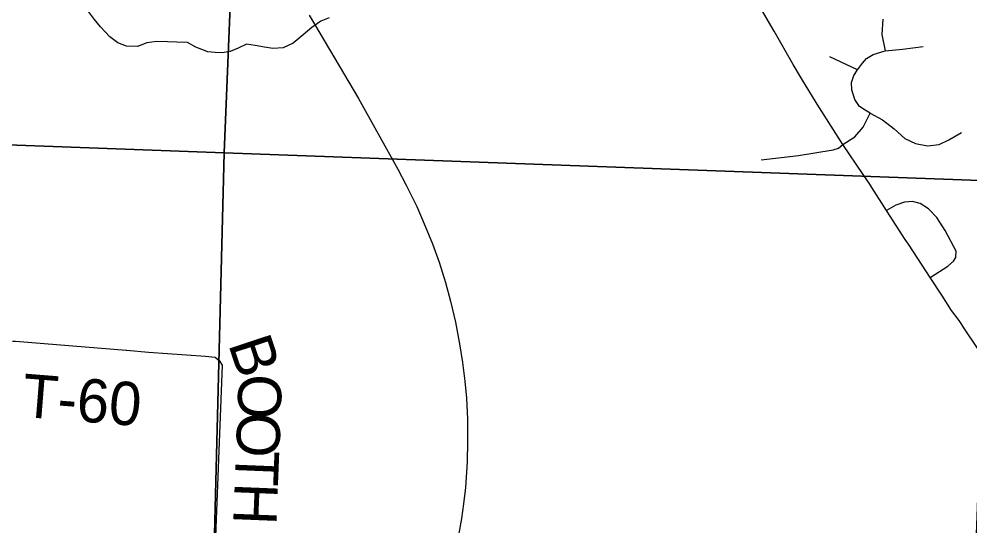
# Model space of a CAD drawing. Extents: x 0 to 34, y 0 to 22.
# Drawn here: x 3.143 to 4.391, y 18.116 to 18.782 of the extents above; entities that cross this region are included whole.
import ezdxf

# ---------------------------------------------------------------- set-up
doc = ezdxf.new("R2010")
doc.units = 0
for name, color, linetype in [('GM_X_City_Street', 7, 'Continuous'), ('GM_X_Minor_River', 7, 'Continuous'), ('GM_X_Rail_Line', 7, 'Continuous'), ('GM_X_Section', 7, 'Continuous'), ('GM_X_Township_Road', 7, 'Continuous'), ('GM_X_Township_Road_Text', 7, 'Continuous'), ('GM_X_US_Route', 7, 'Continuous')]:
    doc.layers.add(name, color=color, linetype=linetype)

msp = doc.modelspace()

# ---------------------------------------------------------------- linework, layer by layer
at = {"layer": 'GM_X_City_Street'}
msp.add_line((4.2444, 18.7152), (4.2082, 18.7319), dxfattribs=at)
for points in [[(4.2776, 18.7814), (4.2764, 18.7616), (4.2809, 18.7398)], [(4.2253, 18.617), (4.2411, 18.6272), (4.2517, 18.64), (4.2609, 18.658), (4.2547, 18.6623), (4.2472, 18.6671), (4.2409, 18.676), (4.237, 18.6888), (4.2367, 18.6983), (4.2396, 18.7077), (4.2444, 18.7152), (4.2508, 18.7237), (4.2563, 18.73), (4.2652, 18.7351), (4.2809, 18.7398), (4.3037, 18.7422), (4.3305, 18.7458)], [(4.2609, 18.658), (4.2772, 18.6495), (4.2925, 18.6377), (4.3065, 18.6248), (4.3204, 18.6183), (4.3363, 18.6154), (4.3515, 18.6172), (4.3642, 18.6231), (4.3809, 18.6329)], [(4.1179, 18.597), (4.167, 18.6024), (4.2124, 18.61), (4.2196, 18.6121), (4.2253, 18.617)]]:
    msp.add_lwpolyline(points, dxfattribs=at)
at = {"layer": 'GM_X_Minor_River'}
msp.add_lwpolyline([(3.5507, 18.7834), (3.5397, 18.779), (3.5278, 18.7708), (3.5166, 18.7608), (3.5032, 18.75), (3.4901, 18.7441), (3.4765, 18.7432), (3.4659, 18.7449), (3.4534, 18.7471), (3.442, 18.7488), (3.4309, 18.7433), (3.4206, 18.7393), (3.4103, 18.7372), (3.4008, 18.7377), (3.3914, 18.7387), (3.3755, 18.7446), (3.3647, 18.7509), (3.3506, 18.7512), (3.3381, 18.7518), (3.3245, 18.7524), (3.3111, 18.7503), (3.2989, 18.7456), (3.2845, 18.7463), (3.2732, 18.7503), (3.2627, 18.7584), (3.2504, 18.7715), (3.2426, 18.7812), (3.2345, 18.7916)], dxfattribs=at)
at = {"layer": 'GM_X_Rail_Line'}
msp.add_lwpolyline([(3.5243, 18.7869), (3.5383, 18.7631), (3.5891, 18.6772), (3.6409, 18.5848), (3.6519, 18.5638), (3.6657, 18.5358), (3.6769, 18.51), (3.6865, 18.4866), (3.6949, 18.4628), (3.7033, 18.436), (3.7101, 18.4114), (3.7163, 18.384), (3.7217, 18.3555), (3.7257, 18.3311), (3.7289, 18.3063), (3.7309, 18.2839), (3.7321, 18.2567), (3.7321, 18.2273), (3.7317, 18.2007), (3.7295, 18.1669), (3.7271, 18.1453), (3.7242, 18.1261), (3.7205, 18.1041)], dxfattribs=at)
at = {"layer": 'GM_X_Section'}
for points in [[(2.4603, 19.6394), (3.4534, 19.6013), (3.4129, 18.6059), (2.4184, 18.643)], [(3.4534, 19.6013), (4.4585, 19.5694), (4.4175, 18.5694), (3.4129, 18.6059)], [(2.4184, 18.643), (3.4129, 18.6059), (3.387, 17.5881), (3.3196, 17.5902), (2.3692, 17.627)], [(3.4129, 18.6059), (4.4175, 18.5694), (4.38, 17.558), (3.387, 17.5881)]]:
    msp.add_lwpolyline(points, close=True, dxfattribs=at)
at = {"layer": 'GM_X_Township_Road'}
for points in [[(4.34, 18.4425), (4.3629, 18.4572), (4.3703, 18.4639), (4.3736, 18.4687), (4.3742, 18.477), (4.3596, 18.5042), (4.3488, 18.5212), (4.3377, 18.5327), (4.3267, 18.5397), (4.3168, 18.542), (4.306, 18.5413), (4.2946, 18.5376), (4.2826, 18.5304)], [(3.1349, 18.3589), (3.1388, 18.3587), (3.2841, 18.347)], [(3.2841, 18.347), (3.2851, 18.3469), (3.3133, 18.3446), (3.3881, 18.3393), (3.4008, 18.3377), (3.4063, 18.3334), (3.4102, 18.3273), (3.3965, 17.9785), (3.397, 17.9675), (3.4018, 17.9608), (3.4098, 17.9541), (3.4222, 17.951), (3.4344, 17.9471), (3.4425, 17.9405), (3.4606, 17.9098), (3.5052, 17.8475), (3.5116, 17.8359), (3.5141, 17.8259), (3.5141, 17.8131), (3.5104, 17.6878), (3.5044, 17.6283), (3.5042, 17.6158), (3.5033, 17.6056), (3.5035, 17.5989)]]:
    msp.add_lwpolyline(points, dxfattribs=at)
at = {"layer": 'GM_X_US_Route'}
for points in [[(4.2605, 18.5649), (4.2517, 18.5778), (4.2253, 18.617), (4.1914, 18.6699), (4.1711, 18.7037), (4.16, 18.722), (4.135, 18.7657), (4.106, 18.8157), (4.0912, 18.8408), (4.0813, 18.8582), (4.0597, 18.8957), (4.0311, 18.9433), (4.0145, 18.973), (4.0034, 18.9916), (3.9906, 19.0137), (3.9768, 19.0398), (3.9701, 19.0526), (3.9627, 19.0693), (3.9616, 19.0732)], [(4.4124, 18.3344), (4.402, 18.3499), (4.3842, 18.3764), (4.3813, 18.3807), (4.378, 18.3858), (4.368, 18.3991), (4.355, 18.4193), (4.34, 18.4425), (4.3293, 18.4585), (4.3112, 18.4863), (4.3072, 18.4923), (4.2826, 18.5304), (4.2634, 18.5607), (4.2605, 18.5649)]]:
    msp.add_lwpolyline(points, dxfattribs=at)

# ---------------------------------------------------------------- texts
at = {"layer": 'GM_X_Township_Road_Text'}
for s, height, rotation, p in [('B', 0.0568, 288.3783, (3.4177, 18.3552)), ('T-60', 0.05682, 355.4118, (3.146, 18.2597)), ('O', 0.0568, 268.612, (3.4316, 18.3161)), ('O', 0.0568, 267.6926, (3.4304, 18.2663)), ('T', 0.0568, 267.6927, (3.4284, 18.2164)), ('H', 0.0568, 267.6926, (3.4267, 18.1739))]:
    msp.add_text(s, height=height, rotation=rotation, dxfattribs=at).set_placement(p)

doc.saveas('drawing.dxf')
